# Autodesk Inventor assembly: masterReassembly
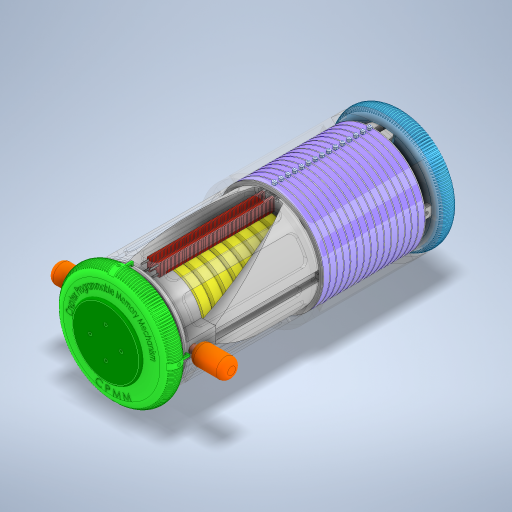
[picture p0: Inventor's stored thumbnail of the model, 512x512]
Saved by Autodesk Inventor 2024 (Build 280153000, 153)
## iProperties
Created: 2021-02
Part Number: masterReassembly
Document SubType Name: Assembly
Designer: ftrauzettel
Author: ftrauzettel
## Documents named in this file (24)
- C:\Users\FabianTrauzettel\OneDrive\Delft\CPMM\Machined_Prototype\Mods\Export\masterReassembly.iam
- C:\Users\FabianTrauzettel\OneDrive\Delft\CPMM\Machined_Prototype\Mods\Export\End knob.ipt
- C:\Users\FabianTrauzettel\OneDrive\Delft\CPMM\Machined_Prototype\Mods\Export\Inner shaft part 3.ipt
- C:\Users\FabianTrauzettel\OneDrive\Delft\CPMM\Machined_Prototype\Mods\Export\Inner shaft part 1.ipt
- C:\Users\FabianTrauzettel\OneDrive\Delft\CPMM\Machined_Prototype\Mods\Export\Inner shaft part 2.ipt
- C:\Users\FabianTrauzettel\OneDrive\Delft\CPMM\Machined_Prototype\Mods\Export\Fixed shaft.ipt
- C:\Users\FabianTrauzettel\OneDrive\Delft\CPMM\Machined_Prototype\Mods\Export\Rotating shaft.ipt
- C:\Users\FabianTrauzettel\OneDrive\Delft\CPMM\Machined_Prototype\Mods\Export\Inner shaft part 4.ipt
- C:\Users\FabianTrauzettel\OneDrive\Delft\CPMM\Machined_Prototype\Mods\Export\Input knob.ipt
- C:\Users\FabianTrauzettel\OneDrive\Delft\CPMM\Machined_Prototype\Mods\Export\pin input knob.ipt
- C:\Users\FabianTrauzettel\OneDrive\Delft\CPMM\Machined_Prototype\Mods\Export\firstMemoryRing.iam
- C:\Users\FabianTrauzettel\OneDrive\Delft\CPMM\Machined_Prototype\Mods\Export\middleMemoryRing.iam
- C:\Users\FabianTrauzettel\OneDrive\Delft\CPMM\Machined_Prototype\Mods\Export\lastMemoryRing.iam
- C:\Users\FabianTrauzettel\OneDrive\Delft\CPMM\Machined_Prototype\Mods\Export\Translational motion part.ipt
- C:\Users\FabianTrauzettel\OneDrive\Delft\CPMM\Machined_Prototype\Mods\Export\Translational motion _ front part(2).ipt
- C:\Users\FabianTrauzettel\OneDrive\Delft\CPMM\Machined_Prototype\Mods\Export\Pin_translational motion.ipt
- C:\Users\FabianTrauzettel\OneDrive\Delft\CPMM\Machined_Prototype\Mods\Export\ringSeparatorCarcass.iam
- C:\Users\FabianTrauzettel\OneDrive\Delft\CPMM\Machined_Prototype\Mods\Export\readingRing.iam
- C:\Users\FabianTrauzettel\OneDrive\Delft\CPMM\Machined_Prototype\Mods\Export\ISO 4762 - M3 x 16ISO.ipt
- C:\Users\FabianTrauzettel\OneDrive\Delft\CPMM\Machined_Prototype\Mods\Export\Tube 1.ipt
- C:\Users\FabianTrauzettel\OneDrive\Delft\CPMM\Machined_Prototype\Mods\Export\Tube 2.ipt
- C:\Users\FabianTrauzettel\OneDrive\Delft\CPMM\Machined_Prototype\Mods\Export\pusher pin.ipt
- C:\Users\FabianTrauzettel\OneDrive\Delft\CPMM\Machined_Prototype\Mods\Export\hbeam subassembly_v0.2.iam
- C:\Users\FabianTrauzettel\OneDrive\Delft\CPMM\Machined_Prototype\Mods\Export\Casing-endpart.ipt
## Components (51 placed, 23 different names)
1. Casing-endpart:1 — Mate:104, Mate:105, Mate:106
2. Tube 2:1 — Mate:97, Mate:106, Mate:107
3. ISO 4762 M3 x 16:1
4. Pin_translational motion:1 — Mate:45, Mate:46, Angle:8, Flush:1, Mate:51
5. Pin_translational motion:2 — Mate:47, Mate:48, Flush:1
6. readingRing:15 [sub-assembly] — Mate:86, Mate:87
7. readingRing:14 [sub-assembly] — Mate:84, Mate:85, Mate:86
8. readingRing:13 [sub-assembly] — Mate:82, Mate:83
9. readingRing:12 [sub-assembly] — Mate:80, Mate:81
10. readingRing:11 [sub-assembly] — Mate:78, Mate:79
11. readingRing:10 [sub-assembly] — Mate:76, Mate:77
12. readingRing:9 [sub-assembly] — Mate:74, Mate:75
13. readingRing:8 [sub-assembly] — Mate:72, Mate:73
14. readingRing:7 [sub-assembly] — Mate:70, Mate:71
15. readingRing:6 [sub-assembly] — Mate:68, Mate:69
16. readingRing:5 [sub-assembly] — Mate:66, Mate:67
17. readingRing:4 [sub-assembly] — Mate:64, Mate:65
18. readingRing:3 [sub-assembly] — Mate:62, Mate:63
19. readingRing:2 [sub-assembly] — Mate:60, Mate:61
20. readingRing:1 [sub-assembly] — Mate:58, Mate:59, Mate:88
21. ringSeparatorCarcass:1 [sub-assembly] — Mate:55, Mate:56, Mate:57, Mate:58, Mate:59, Mate:60, Mate:61, Mate:62, Mate:63, Mate:64, Mate:65, Mate:66, Mate:67, Mate:68, Mate:69, Mate:70, Mate:71, Mate:72, Mate:73, Mate:74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
22. Rotating shaft:1 — Mate:12, Mate:13, Mate:20, Mate:21, Mate:37
23. Fixed shaft:1 — Mate:9, Mate:10, Mate:11, Mate:13
24. Inner shaft part 2:2 — Mate:14, Mate:15, Mate:16, Mate:17, Mate:18
25. Inner shaft part 2:1 — Mate:4, Mate:5, Mate:6, Mate:7
26. Inner shaft part 1:1 — Mate:7, Mate:8, Mate:9, Mate:12, Mate:17, Mate:18, Mate:19
27. Inner shaft part 3:1 — Mate:1, Mate:2, Mate:3, Mate:4, Mate:5, Mate:6
28. Translational motion part:1
29. firstMemoryRing:1 [sub-assembly] — Mate:25, Mate:26, Angle:1, Mate:37, Mate:44
30. middleMemoryRing:1 [sub-assembly] — Mate:25, Mate:26, Mate:27, Mate:28, Angle:1, Angle:2
31. middleMemoryRing:2 [sub-assembly] — Mate:27, Mate:28, Mate:29, Mate:30, Angle:2, Angle:3
32. middleMemoryRing:3 [sub-assembly] — Mate:29, Mate:30, Mate:31, Mate:32, Angle:3, Angle:4
33. middleMemoryRing:4 [sub-assembly] — Mate:31, Mate:32, Mate:33, Mate:34, Angle:4, Angle:5
34. middleMemoryRing:5 [sub-assembly] — Mate:33, Mate:34, Angle:5, Mate:38, Mate:39, Angle:6
35. middleMemoryRing:6 [sub-assembly] — Mate:38, Mate:39, Angle:6, Mate:40, Mate:41, Angle:7
36. lastMemoryRing:1 [sub-assembly] — Mate:40, Mate:41, Angle:7, Mate:88
37. pusher pin:1 — Mate:100, Tangent:2
38. pusher pin:2 — Mate:101, Tangent:1
39. Translational motion _ front part(2):1 — Mate:49, Mate:50, Mate:51, Mate:100, Mate:101, Tangent:1, Tangent:2
40. Tube 1:1 — Mate:95, Mate:96, Mate:97, Mate:99, Mate:107
41. Inner shaft part 4:1 — Mate:14, Mate:15, Mate:16
42. Input knob:1
43. End knob:1
44. ISO 4762 M3 x 16:2
45. ISO 4762 M3 x 16:3
46. pin input knob:3 — Mate:22, Mate:23, Mate:24
47. pin input knob:5
48. pin input knob:6
49. pin input knob:7
50. hbeam subassembly_v0.2:1 [sub-assembly] — Mate:102, Mate:103, Angle:9
51. hbeam subassembly_v0.2:2 [sub-assembly]
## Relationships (105: Mate 93, Angle 9, Tangent 2, Flush 1)
- Mate:1: Inner shaft part 3:1
- Mate:2: Inner shaft part 3:1
- Mate:3: Inner shaft part 3:1
- Mate:4: Inner shaft part 2:1 ↔ Inner shaft part 3:1
- Mate:5: Inner shaft part 2:1 ↔ Inner shaft part 3:1
- Mate:6: Inner shaft part 2:1 ↔ Inner shaft part 3:1
- Mate:7: Inner shaft part 2:1 ↔ Inner shaft part 1:1
- Mate:8: Inner shaft part 1:1
- Mate:9: Fixed shaft:1 ↔ Inner shaft part 1:1
- Mate:10: Fixed shaft:1
- Mate:11: Fixed shaft:1
- Mate:12: Rotating shaft:1 ↔ Inner shaft part 1:1
- Mate:13: Rotating shaft:1 ↔ Fixed shaft:1
- Mate:14: Inner shaft part 2:2 ↔ Inner shaft part 4:1
- Mate:15: Inner shaft part 2:2 ↔ Inner shaft part 4:1
- Mate:16: Inner shaft part 2:2 ↔ Inner shaft part 4:1
- Mate:17: Inner shaft part 2:2 ↔ Inner shaft part 1:1
- Mate:18: Inner shaft part 2:2 ↔ Inner shaft part 1:1
- Mate:19: Inner shaft part 1:1
- Mate:20: Rotating shaft:1
- Mate:21: Rotating shaft:1
- Mate:22: pin input knob:3
- Mate:23: pin input knob:3
- Mate:24: pin input knob:3
- Mate:25: firstMemoryRing:1 ↔ middleMemoryRing:1
- Mate:26: firstMemoryRing:1 ↔ middleMemoryRing:1
- Mate:27: middleMemoryRing:1 ↔ middleMemoryRing:2
- Mate:28: middleMemoryRing:1 ↔ middleMemoryRing:2
- Mate:29: middleMemoryRing:2 ↔ middleMemoryRing:3
- Mate:30: middleMemoryRing:2 ↔ middleMemoryRing:3
- Mate:31: middleMemoryRing:3 ↔ middleMemoryRing:4
- Mate:32: middleMemoryRing:3 ↔ middleMemoryRing:4
- Mate:33: middleMemoryRing:4 ↔ middleMemoryRing:5
- Mate:34: middleMemoryRing:4 ↔ middleMemoryRing:5
- Angle:1: firstMemoryRing:1 ↔ middleMemoryRing:1
- Angle:2: middleMemoryRing:1 ↔ middleMemoryRing:2
- Angle:3: middleMemoryRing:2 ↔ middleMemoryRing:3
- Angle:4: middleMemoryRing:3 ↔ middleMemoryRing:4
- Angle:5: middleMemoryRing:4 ↔ middleMemoryRing:5
- Mate:37: Rotating shaft:1 ↔ firstMemoryRing:1
- Mate:38: middleMemoryRing:5 ↔ middleMemoryRing:6
- Mate:39: middleMemoryRing:5 ↔ middleMemoryRing:6
- Angle:6: middleMemoryRing:5 ↔ middleMemoryRing:6
- Mate:40: middleMemoryRing:6 ↔ lastMemoryRing:1
- Mate:41: middleMemoryRing:6 ↔ lastMemoryRing:1
- Angle:7: middleMemoryRing:6 ↔ lastMemoryRing:1
- Mate:44: firstMemoryRing:1
- Mate:45: Pin_translational motion:1
- Mate:46: Pin_translational motion:1
- Angle:8: Pin_translational motion:1
- Mate:47: Pin_translational motion:2
- Mate:48: Pin_translational motion:2
- Flush:1: Pin_translational motion:1 ↔ Pin_translational motion:2
- Mate:49: Translational motion _ front part(2):1
- Mate:50: Translational motion _ front part(2):1
- Mate:51: Pin_translational motion:1 ↔ Translational motion _ front part(2):1
- Mate:55: ringSeparatorCarcass:1
- Mate:56: ringSeparatorCarcass:1
- Mate:57: ringSeparatorCarcass:1
- Mate:58: readingRing:1 ↔ ringSeparatorCarcass:1
- Mate:59: readingRing:1 ↔ ringSeparatorCarcass:1
- Mate:60: readingRing:2 ↔ ringSeparatorCarcass:1
- Mate:61: readingRing:2 ↔ ringSeparatorCarcass:1
- Mate:62: readingRing:3 ↔ ringSeparatorCarcass:1
- Mate:63: readingRing:3 ↔ ringSeparatorCarcass:1
- Mate:64: readingRing:4 ↔ ringSeparatorCarcass:1
- Mate:65: readingRing:4 ↔ ringSeparatorCarcass:1
- Mate:66: readingRing:5 ↔ ringSeparatorCarcass:1
- Mate:67: readingRing:5 ↔ ringSeparatorCarcass:1
- Mate:68: readingRing:6 ↔ ringSeparatorCarcass:1
- Mate:69: readingRing:6 ↔ ringSeparatorCarcass:1
- Mate:70: readingRing:7 ↔ ringSeparatorCarcass:1
- Mate:71: readingRing:7 ↔ ringSeparatorCarcass:1
- Mate:72: readingRing:8 ↔ ringSeparatorCarcass:1
- Mate:73: readingRing:8 ↔ ringSeparatorCarcass:1
- Mate:74: readingRing:9 ↔ ringSeparatorCarcass:1
- Mate:75: readingRing:9 ↔ ringSeparatorCarcass:1
- Mate:76: readingRing:10 ↔ ringSeparatorCarcass:1
- Mate:77: readingRing:10 ↔ ringSeparatorCarcass:1
- Mate:78: readingRing:11 ↔ ringSeparatorCarcass:1
- Mate:79: readingRing:11 ↔ ringSeparatorCarcass:1
- Mate:80: readingRing:12 ↔ ringSeparatorCarcass:1
- Mate:81: readingRing:12 ↔ ringSeparatorCarcass:1
- Mate:82: readingRing:13 ↔ ringSeparatorCarcass:1
- Mate:83: readingRing:13 ↔ ringSeparatorCarcass:1
- Mate:84: readingRing:14 ↔ ringSeparatorCarcass:1
- Mate:85: readingRing:14 ↔ ringSeparatorCarcass:1
- Mate:86: readingRing:15 ↔ readingRing:14
- Mate:87: readingRing:15 ↔ ringSeparatorCarcass:1
- Mate:88: readingRing:1 ↔ lastMemoryRing:1
- Mate:95: Tube 1:1
- Mate:96: Tube 1:1
- Mate:97: Tube 2:1 ↔ Tube 1:1
- Mate:99: Tube 1:1
- Mate:100: pusher pin:1 ↔ Translational motion _ front part(2):1
- Mate:101: pusher pin:2 ↔ Translational motion _ front part(2):1
- Tangent:1: pusher pin:2 ↔ Translational motion _ front part(2):1
- Tangent:2: pusher pin:1 ↔ Translational motion _ front part(2):1
- Mate:102: hbeam subassembly_v0.2:1
- Mate:103: hbeam subassembly_v0.2:1
- Angle:9: hbeam subassembly_v0.2:1
- Mate:104: Casing-endpart:1 ↔ ringSeparatorCarcass:1
- Mate:105: Casing-endpart:1 ↔ ringSeparatorCarcass:1
- Mate:106: Casing-endpart:1 ↔ Tube 2:1
- Mate:107: Tube 2:1 ↔ Tube 1:1
